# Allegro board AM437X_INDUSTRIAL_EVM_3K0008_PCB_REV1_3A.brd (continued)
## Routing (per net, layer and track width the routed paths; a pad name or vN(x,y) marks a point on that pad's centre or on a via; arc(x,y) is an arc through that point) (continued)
JTAG_TMS: length 66.6
  TOP w0.13: J7.1 v1(133.6,74.42) ; U11.Y24 84.72,74.62 84.72,78.06 85.2,78.55 v1(85.2,80.02)
  L3_SIG1 w0.13: v1(126.54,73.69) 125.78,72.92 121.94,72.92 120.24,74.61 110.81,74.61 v1(107.95,77.47)
  L4_SIG2 w0.13: v1(126.54,73.69) 129.31,70.92 130.1,70.92 v1(133.6,74.42)
  BOTTOM w0.13: v1(107.95,77.47) 105.23,77.47 103.94,78.76 103.94,79.86 102.19,81.61 98.43,81.61 96.69,79.86 94.02,79.86 93.47,80.41 86.11,80.41 85.71,80.01 85.21,80.01 v1(85.2,80.02) ; v1(126.54,73.69) 126.26,73.69 125.77,73.19 U45.11
JTAG_TRSTN: length 66.7
  TOP w0.13: U11.Y25 85.03,78.01 85.75,78.73 v1(85.75,80.8) ; J7.2 v1(128.4,74.42)
  L3_SIG1 w0.13: v1(106.3,77.98) 107.31,76.96 107.95,76.96 110.63,74.28 110.63,73.78 110.94,73.47 114.34,73.47 114.44,73.57 119.13,73.57 120.14,72.56 120.78,72.56 121.42,71.92 124.75,71.92 v1(125.73,70.94)
  L4_SIG2 w0.13: v1(128.4,74.42) 127.75,75.07 125.15,75.07 124.7,74.62 124.7,73.78 125.09,73.38 125.09,71.58 v1(125.73,70.94)
  BOTTOM w0.13: R433.2 v1(128.4,74.42) ; v1(125.73,70.94) 125.73,70.94 125.12,71.55 U45.10 ; v1(85.75,80.8) 85.76,80.79 93.7,80.79 94.33,80.17 96.5,80.17 98.24,81.91 103.07,81.91 104.49,80.49 104.49,79.15 105.66,77.98 v1(106.3,77.98)
JTAGPOD_DET: length 9.7
  TOP w0.13: v1(121.01,82.22) 120.52,82.7 120.52,84.15 120.2,84.47 U8.4
  BOTTOM w0.13: R421.1 124.87,78.36 v1(121.01,82.22)
MMC_CD: length 110.3
  TOP w0.13: v1(83.69,84.96) 83.82,84.84 R84.1
  L4_SIG2 w0.13: v1(46.99,40) 48.42,41.44 48.42,50.27 48.26,50.43 48.26,54.29 48.88,54.9 48.88,55.74 49.19,56.05 49.19,56.88 49.53,57.23 49.95,57.23 53.35,60.63 55.38,60.63 55.69,60.93 59.3,60.93 60.11,61.74 60.11,63.71 64.57,68.17 64.57,71.94 66.56,73.93 67.44,73.93 67.65,74.14 72.28,74.14 72.52,74.39 72.52,74.63 74.6,76.7 74.6,80.57 73.76,81.4 73.76,85.93 75.19,87.36 77.33,87.36 78.58,86.11 81.25,86.11 81.88,85.47 83.19,85.47 v1(83.69,84.96)
  BOTTOM w0.13: 52.88,19.17 53.21,19.5 53.21,21.21 52.61,21.81 52.61,23.48 54.36,25.22 54.36,34.29 51.24,37.41 50.27,37.41 49.71,37.97 48.39,37.97 46.99,39.37 v1(46.99,40) ; 52.88,19.17 53.48,18.57 54.31,18.57 54.49,18.39 54.49,17.15 54.23,16.89 R548.1 53.59,16.39 54.49,15.49 J19.10 ; 52.88,19.17 U59.3
MMC_CLK: length 67.8
  TOP w0.13: U27.1 v1(46.06,5.58) 45.72,5.92 45.72,6.73 46.1,7.11 51.78,7.11 54.48,9.82 54.48,15.11 54.71,15.34 54.71,17.81 55.65,18.75 55.65,20.22 56.74,21.3 56.74,24.14 55.89,24.98 55.89,30.09 56.24,30.43 56.24,30.94 56.39,31.09 57.15,31.09 57.3,31.25 57.3,31.46 57.15,31.61 56.39,31.61 56.24,31.77 56.24,31.98 56.39,32.14 57.15,32.14 57.3,32.29 57.3,32.5 57.15,32.66 56.39,32.66 56.24,32.81 56.24,33.03 56.39,33.18 57.15,33.18 57.3,33.33 57.3,33.55 57.15,33.7 56.39,33.7 56.24,33.85 56.24,41.41 59.49,44.65 59.49,48.13 60.25,48.89 R179.1
  BOTTOM w0.13: v1(46.06,5.58) 46.06,5.01 43.72,2.66 J19.5
MMC_CMD: length 66.7
  TOP w0.13: v1(52.83,9.02) 54.05,10.23 54.05,15.39 54.25,15.6 54.25,17.98 55.19,18.92 55.19,20.4 56.26,21.46 56.26,23.95 55.46,24.75 55.46,30.27 55.81,30.61 55.81,42.09 58.72,45.01 58.72,45.29 58.57,45.44 58.24,45.44 58.09,45.59 58.09,45.81 58.24,45.96 58.57,45.96 58.72,46.11 58.72,46.33 58.57,46.48 58.24,46.48 58.09,46.64 58.09,46.85 58.24,47 58.57,47 58.72,47.16 58.72,47.37 58.57,47.53 58.24,47.53 58.09,47.68 58.09,47.89 58.24,48.05 58.57,48.05 58.72,48.2 58.72,48.41 58.57,48.57 58.24,48.57 58.09,48.72 58.09,48.94 58.24,49.09 58.57,49.09 58.72,49.24 58.72,49.63 59.13,50.04 R177.1 ; v1(50.42,4.58) U27.7 ; R244.1 v1(51.05,9.02)
  L3_SIG1 w0.13: v1(52.83,9.02) v1(51.05,9.02) 50.42,8.38 v1(50.42,4.58)
  BOTTOM w0.13: J19.3 53.79,3.36 52.55,4.6 50.44,4.6 v1(50.42,4.58)
MMC_D0: length 68.6
  TOP w0.13: U27.2 45.46,5.08 v1(45.21,4.83) ; v1(45.21,4.83) R267.1 ; v1(45.21,4.83) 45.21,5.52 45.21,5.53 45.21,6.84 45.92,7.55 51.6,7.55 52.32,8.27 52.32,9.53 53.47,10.67 53.47,15.49 53.8,15.82 53.8,19.69 55.82,21.71 55.82,23.75 55.02,24.55 55.02,30.45 55.37,30.79 55.37,42.64 57.61,44.87 57.61,47.02 57.45,47.18 57.2,47.18 57.05,47.33 57.05,47.54 57.2,47.7 57.45,47.7 57.61,47.85 57.61,48.07 57.45,48.22 57.2,48.22 57.05,48.37 57.05,48.59 57.2,48.74 57.45,48.74 57.61,48.89 57.61,49.11 57.45,49.26 57.2,49.26 57.05,49.41 57.05,49.63 57.2,49.78 57.45,49.78 57.61,49.93 57.61,50.37 58.42,51.18 R174.1
  BOTTOM w0.13: v1(45.21,4.83) 44.45,4.06 J19.7
MMC_D1: length 72.6
  TOP w0.13: R167.1 57.35,52.32 56.59,51.56 56.59,51.14 56.44,50.99 55.8,50.99 55.65,50.83 55.65,50.62 55.8,50.47 56.44,50.47 56.59,50.31 56.59,50.1 56.44,49.94 55.8,49.94 55.65,49.79 55.65,49.58 55.8,49.42 56.44,49.42 56.59,49.27 56.59,44.47 54.94,42.82 54.94,30.97 54.59,30.63 54.59,24.3 55.39,23.5 55.39,21.91 53.34,19.86 53.34,16.05 53.01,15.73 53.01,10.98 51.82,9.78 51.82,8.51 51.31,8 43.69,8 42.54,6.86 42.54,5.53 42.55,5.52 v1(42.55,4.83) R266.1 43.94,4.19 45.34,4.19 45.72,4.58 U27.3
  BOTTOM w0.13: v1(42.55,4.83) 41.32,4.83 J19.8
MMC_D2: length 76.9
  TOP w0.13: U27.6 v1(49.02,4.08) ; R161.1 57.25,53.47 54.99,51.21 54.99,49.35 55.8,48.55 55.8,48.07 55.64,47.91 55.04,47.91 54.89,47.76 54.89,47.55 55.04,47.39 55.64,47.39 55.8,47.24 55.8,47.02 55.64,46.87 55.04,46.87 54.89,46.72 54.89,46.5 55.04,46.35 55.64,46.35 55.8,46.2 55.8,45.98 55.64,45.83 55.04,45.83 54.89,45.68 54.89,45.46 55.04,45.31 55.64,45.31 55.8,45.16 55.8,44.29 54.5,43 54.5,37.67 53.78,36.95 53.78,34.68 54.5,33.96 54.5,31.16 54.15,30.81 54.15,24.05 54.95,23.25 54.95,22.11 52.88,20.04 52.88,16.26 52.58,15.95 52.58,11.68 v1(51.05,10.16) R236.1
  L3_SIG1 w0.13: v1(51.05,10.16) 50.43,10.78 48.07,10.78 47.5,10.21 47.5,7.37 49.02,5.84 v1(49.02,4.08) 50.62,4.08 51.31,4.76 v1(54.74,4.76)
  BOTTOM w0.13: J19.1 v1(54.74,4.76)
MMC_D3: length 72.6
  TOP w0.13: U27.8 v1(49.66,5.08) ; R231.1 v1(51.05,11.43) 52.07,12.45 52.07,16.15 52.43,16.51 52.43,21.31 53.72,22.6 53.72,30.99 54.07,31.34 54.07,33.78 53.21,34.63 53.21,36.99 54.07,37.85 54.07,43.18 54.43,43.55 54.43,49.22 54.28,49.37 53.52,49.37 53.37,49.53 53.37,49.74 53.52,49.89 54.28,49.89 54.43,50.05 54.43,50.26 54.28,50.41 53.52,50.41 53.37,50.57 53.37,50.78 53.52,50.94 54.28,50.94 54.43,51.09 54.43,51.51 56.9,53.98 61.6,53.98 R158.1
  L3_SIG1 w0.13: v1(51.05,11.43) 52.07,10.41 52.07,9.91 51.72,9.55 50.07,9.55 49.66,9.14 v1(49.66,5.08)
  BOTTOM w0.13: J19.2 55.77,4.06 53.85,4.06 52.84,5.08 v1(49.66,5.08)
MOT1_ADC: length 201
  TOP w0.13: v2(108.84,73.91) 107.15,72.23 107.15,70.73 106.8,70.38 106.8,69.33 105.5,68.04 103.54,68.04 v2(103.25,68.33)
  TOP w0.203: U11.Y13 84.7,67.48 v1(84.7,67.5)
  L3_SIG1 w0.13: v1(26.39,9.24) 27.83,7.8 41.99,7.8 46.5,12.31 50.93,12.31 52.7,10.54 52.7,9.9 56.38,6.23 66.05,6.23 67.58,7.77 69.47,7.77 70.9,9.19 75.51,9.19 77.84,6.87 88.67,6.87 88.85,7.05 103.75,7.05 105.95,9.26 105.95,11.43 109.66,15.13 109.66,20.28 111.87,22.49 111.87,24.38 115.37,27.89 120.9,27.89 122.17,29.16 v1(122.17,31.06) ; v1(84.7,67.5) 85.35,66.85 97.71,66.85 98.55,67.69 102.62,67.69 v2(103.25,68.33)
  L4_SIG2 w0.13: v2(103.25,68.33) 104.01,68.33 104.96,67.38 105.35,67.38 106.56,66.17 107.92,66.17 108.67,65.42 110.51,65.42 111.83,64.09 111.83,63.39 115.4,59.82 115.4,55.72 117.04,54.09 117.04,48.43 115.88,47.28 115.88,39.83 117.18,38.53 117.18,35.28 118.02,34.44 120.39,34.44 122.17,32.66 v1(122.17,31.06)
  BOTTOM w0.13: R561.2 v1(26.39,9.24)
  BOTTOM w0.254: R435.2 v2(108.84,73.91)
MOT1_LEVEL: length 3.4
  BOTTOM w0.13: R561.1 R562.1 C349.1 R554.2
MOT2_ADC: length 177.9
  TOP w0.13: U11.AD13 87.94,66.84 89.5,66.84 90.04,66.29 94.64,66.29 95.47,67.12 100.24,67.12 100.76,66.6 v1(104.27,66.6) R129.2
  L3_SIG1 w0.13: v1(31.74,9.15) 39.81,9.15 43.59,12.93 51.19,12.93 53.32,10.79 53.32,10.16 56.63,6.85 65.79,6.85 67.33,8.38 69.22,8.38 70.64,9.81 75.77,9.81 76.7,8.88 76.91,8.67 77.25,8.32 90.47,8.32 91.12,7.67 103.49,7.67 105.34,9.51 105.34,11.68 109.05,15.39 109.05,20.54 111.25,22.74 111.25,24.64 115.12,28.51 119.62,28.51 v1(120.5,29.39)
  L4_SIG2 w0.13: v1(104.27,66.6) 104.76,66.11 105.27,66.11 105.6,65.77 105.6,65.4 106.29,64.7 106.81,64.7 106.9,64.8 110.25,64.8 111.22,63.84 111.22,63.13 114.79,59.56 114.79,54.22 115.08,53.93 115.08,50.54 115.79,49.84 115.79,48.06 114.91,47.18 114.91,44.8 115.27,44.44 115.27,39.57 116.54,38.3 116.54,34.99 117.15,34.39 117.9,33.63 120.32,33.63 120.83,33.12 120.83,29.72 v1(120.5,29.39)
  BOTTOM w0.13: R563.2 v1(31.74,9.15)
MOT2_LEVEL: length 3.4
  BOTTOM w0.13: R563.1 R564.1 R555.2 C350.1
MOT3_ADC: length 175.7
  TOP w0.13: U11.AE13 89.82,67.15 90.42,66.55 94.46,66.55 95.34,67.43 100.5,67.43 v1(101.27,68.2) 101.32,68.2 102.21,69.09 103.76,69.09 R124.2
  L3_SIG1 w0.13: v1(121.51,29.77) 121.51,29.39 120.32,28.2 115.25,28.2 111.56,24.51 111.56,22.62 109.35,20.41 109.35,15.26 105.65,11.55 105.65,9.38 103.62,7.36 91,7.36 90.34,8.02 77.13,8.02 75.64,9.5 70.77,9.5 69.34,8.07 67.46,8.07 65.92,6.54 56.5,6.54 53.01,10.03 53.01,10.67 51.06,12.62 45.83,12.62 41.72,8.51 v1(38.73,8.51)
  L4_SIG2 w0.13: v1(121.51,29.77) 121.51,32.88 120.46,33.94 118.03,33.94 117.96,34 116.85,35.12 116.85,38.43 115.58,39.7 115.58,47.41 116.66,48.49 116.66,52.79 115.09,54.35 115.09,59.69 111.52,63.26 111.52,63.97 110.38,65.11 108.4,65.11 107.66,65.85 105.96,65.85 104.74,67.07 104.07,67.07 103.78,66.78 102.72,66.78 101.3,68.2 v1(101.27,68.2)
  BOTTOM w0.13: R558.2 v1(38.73,8.51)
MOT3_LEVEL: length 3.4
  BOTTOM w0.13: C348.1 R553.2 R559.1 R558.1
MOT_OUT1: length 2.3
  TOP w0.254: U23.5 40.79,26.67
MOT_OUT2: length 2.3
  TOP w0.305: U23.8 42.74,27.12 42.42,26.8
MOT_OUT3: length 2.9
  TOP w0.305: U23.9 43.39,27.35 44.32,26.42
MOT_PGND1: length 36.3
  TOP w0.305: v1(41.61,26.92) 41.61,27.3 41.44,27.47 U23.6
  TOP w0.508: R195.2 v1(57.78,34.54)
  L4_SIG2 w0.508: v1(41.61,26.92) 41.61,25.2 45.8,21.01 52.88,21.01 v3(54.36,22.48)
  BOTTOM w0.508: v3(54.36,22.48) 55.69,23.81 55.69,33.33 56.9,34.54 v1(57.78,34.54) C308.1 ; R538.1 40.41,25.93 41.4,26.92 v1(41.61,26.92)
MOT_PGND2: length 25.8
  TOP w0.305: v1(42.09,27.79) U23.7
  TOP w0.508: R193.2 v1(25.27,34.42)
  L3_SIG1 w0.508: v1(42.09,27.79) 42.06,27.79 41.33,28.52 38.76,28.52 37.08,30.2 37.08,31.8 34.47,34.42 v1(25.27,34.42)
  BOTTOM w0.508: R193.2 v1(25.27,34.42) ; v1(42.09,27.79) 42.55,27.34 42.55,26.57 R537.1
MOT_PGND3: length 21
  TOP w0.305: v1(44.3,27.58) 44.04,27.84 U23.10
  TOP w0.508: R211.2 v1(57.25,25.5)
  L4_SIG2 w0.508: v1(44.3,27.58) 44.3,27.46 45.09,26.67 48.13,26.67 51.05,23.75 52.45,23.75 52.53,23.83 52.53,23.83 53.22,24.51 56.26,24.51 v1(57.25,25.5)
  BOTTOM w0.381: v1(44.3,27.58) 44.3,27.3 45.66,25.93 R536.1
  BOTTOM w0.508: R211.2 v1(57.25,25.5)
MOT_PGNDTOTAL: length 32.1
  TOP w0.508: R200.2 v3(26.16,31.5) ; R215.1 v3(47.62,22.61) ; 52.45,28.83 v3(52.45,28.05) ; R203.2 v3(58.93,31.12) ; R222.2 v3(58.93,21.84)
  L3_SIG1 w0.508: v3(24.38,36.32) 24.38,33.27 v3(26.16,31.5) 29.08,28.58 34.29,28.58 v3(40.64,22.23)
  BOTTOM w0.508: 52.45,28.83 v3(52.45,28.05) ; C332.2 57.44,27.05 v3(57.06,27.43) ; v3(58.93,32.89) 58.67,32.64 C308.2 ; C300.2 v3(24.38,36.32)
MOTOR_OUT1: length 7.2
  TOP w0.508: J17.1 25.78,5.34 ; J17.1 25.78,3.05 ; J17.1 23.49,3.05 ; J17.1 23.49,5.34
  BOTTOM w0.508: R562.2 v3(23.71,9.24)
MOTOR_OUT2: length 5.7
  TOP w0.508: 28.86,5.05 J17.2 ; J17.2 30.58,5.05 ; J17.2 30.58,3.33 ; J17.2 28.86,3.33
  BOTTOM w0.508: R564.2 v3(28.96,9.15)
MOTOR_OUT3: length 5.8
  TOP w0.508: 33.94,5.05 J17.3 ; J17.3 33.94,3.33 ; J17.3 35.66,5.05 ; J17.3 35.66,3.33
  BOTTOM w0.508: R559.2 v3(37.59,8.51)
MOTVM_ADC: length 11.8
  TOP w0.13: v1(103.76,58.17) C68.1 R154.1
  BOTTOM w0.13: R476.2 103.63,58.04 v1(103.76,58.17) 104.52,58.93 104.52,62.86 R454.1
MTR_FAULT: length 386.4
  TOP w0.13: R245.2 v1(83.95,10.54) ; v1(44.69,35.81) U23.18 ; v1(75.94,66.32) U11.F11 ; R62.2 R61.2 R60.2 82.68,92.58 83.44,93.34 v1(83.44,96.14) ; v1(40.77,40.64) 41.78,39.62 R186.1
  L3_SIG1 w0.13: v1(31.88,44.7) 28.03,48.55 28.03,53.05 26.08,54.99 23.75,54.99 20.1,58.64 20.1,61.98 17.25,64.83 17.25,65.56 16.23,66.58 14.83,66.58 13.56,67.85 12.76,67.85 11.75,68.86 11.75,77.54 10.92,78.36 10.92,81.85 11.75,82.68 11.75,84.39 10.03,86.11 10.03,96.77 11.57,98.31 11.57,99.81 10.66,100.72 3.92,100.72 2.29,102.36 2.29,109.09 3.76,110.56 9.61,110.56 13.08,114.04 19.37,114.04 21.87,111.54 21.87,107.47 24.4,104.94 25.73,104.94 28.75,107.95 42.19,107.95 45.37,104.77 56.25,104.77 59.56,108.08 63.32,108.08 64.91,109.67 79.87,109.67 81.91,107.62 v1(81.91,106.68)
  L4_SIG2 w0.13: v1(81.91,106.68) 82.05,106.54 82.05,102.23 82.19,102.09 82.19,97.38 v1(83.44,96.14) ; v1(83.95,10.54) 87.12,13.72 90.3,13.72 93.73,17.14 93.73,21.59 97.65,25.52 97.65,32.33 97.13,32.86 97.13,34.82 96.57,35.38 95.8,35.38 93.99,37.18 93.99,37.19 93.64,37.54 93.64,37.95 91.55,40.04 91.55,40.48 90.82,41.22 90.82,47.28 89.9,48.2 88.6,48.2 87.74,49.05 87.74,53.34 86.7,54.38 86.7,58.05 86.18,58.57 86.18,60.8 86.18,60.8 86.18,61.13 87.02,61.97 87.02,63.43 85.53,64.92 82.61,64.92 82.29,64.59 77.87,64.59 76.67,65.79 76.46,65.79 v1(75.94,66.32) ; v1(44.69,35.81) 44.69,34.79 44.14,34.24 37.09,34.24 31.88,39.45 v1(31.88,44.7)
  BOTTOM w0.13: Q10.G 38.61,41.34 38.61,40 40.13,40 v1(40.77,40.64) 41.91,40.64 44.69,37.86 v1(44.69,35.81) 44.73,35.85 46.52,35.85 48.25,37.58 49.66,37.58 50.14,37.1 51.04,37.1 53.96,34.17 53.96,25.27 49.4,20.7 49.4,15.21 56.87,7.75 62.57,7.75 63.78,8.96 70.43,8.96 71.27,9.8 82.31,9.8 83.06,10.54 v1(83.95,10.54)
MTRA_GND: length 8.7
  L3_SIG1 w0.508: 13.49,37.44 J10.1 ; J10.1 15.13,39.09 ; J10.1 15.13,37.44 ; 10.5,39.96 J10.5 8.85,41.61
  BOTTOM w0.508: C270.2 v3(7.37,48.64) ; v3(19.04,29.08) R513.1 v3(18.03,30.1)
OSC0_IN: length 6.4
  TOP w0.13: R92.2 R82.2 C36.1 72.99,86.83 72.99,88.61 74.05,89.67 Y1.3
OSC0_OUT: length 4.4
  TOP w0.13: Y1.1 71.95,88.07 72.36,87.66 C35.1 72.48,86.2 R82.1 R91.2
PHY1_LED_ACTN: length 39.9
  TOP w0.13: v1(48.47,93.13) 48.48,93.12 49,93.12 R53.2
  L3_SIG1 w0.13: v1(35.69,115.7) 35.69,114.07 39.9,109.86 41.22,109.86 43.63,107.44 v1(46.2,107.44)
  BOTTOM w0.13: U37.17 48.09,93.46 48.43,93.13 v1(48.47,93.13) 48.62,92.98 49.13,92.98 R53.2 49.53,93.09 49.53,93.15 49.98,93.6 50.04,93.6 50.06,93.62 52.48,93.62 53.04,94.19 53.04,99.93 46.2,106.77 v1(46.2,107.44) ; R270.1 v1(35.69,115.7)
PHY1_LED_LINKN: length 33.7
  TOP w0.13: v1(48.64,96.27) R45.2
  L3_SIG1 w0.13: v1(36.83,115.7) 36.83,113.59 40.19,110.24 41.27,110.24 43.31,108.2 v1(46.18,108.2)
  BOTTOM w0.13: v1(48.64,96.27) 49.45,97.07 49.45,103 45.71,106.74 45.71,107.73 v1(46.18,108.2) ; v1(48.64,96.27) R45.2 ; v1(48.64,96.27) 48.64,95.12 47.98,94.46 U37.15 ; R269.1 v1(36.83,115.7)
PORZ_RELEASE: length 101.7
  TOP w0.13: v1(66.88,10.46) 65.9,11.45 U26.16
  L3_SIG1 w0.13: v1(137.16,39.12) 130.18,32.13 122.24,32.13 118.92,28.81 114.99,28.81 110.94,24.77 110.94,22.87 108.74,20.67 108.74,17.71 105.03,14 105.03,10.87 103.11,8.96 100.63,8.96 99.65,7.97 91.25,7.97 90.6,8.63 77.38,8.63 75.56,10.45 66.89,10.45 v1(66.88,10.46)
  BOTTOM w0.13: v1(137.16,39.12) 136.78,39.5 136.78,46.48 135.89,47.37 R487.1
PORZN: length 158.8
  TOP w0.13: R90.2 v1(85.6,85.09) 85.72,85.22 R75.1
  L3_SIG1 w0.13: v1(65.32,79.17) 65.43,79.06 66.07,79.06 66.53,79.52 66.53,80.49 65.62,81.39 65.62,85.61 65.14,86.09 65.14,87.67 65.84,88.37 68.4,88.37 70.15,90.12 v1(76.45,90.12) ; v1(120.78,34.85) 122.73,32.89 129.92,32.89 v1(136.02,38.99)
  L4_SIG2 w0.13: v1(85.6,85.09) 86.61,85.09 86.87,84.84 91.19,84.84 95.91,80.11 96.56,80.11 98.38,78.29 99.42,78.29 99.89,77.82 99.89,75.02 100.44,74.47 100.44,71.39 101.12,70.71 102.75,70.71 103.53,69.93 103.53,69.46 105.13,67.87 106.65,67.87 108.44,66.08 v2(109.69,66.08) 110.29,66.08 112.14,64.22 112.14,63.88 115.71,60.31 115.71,55.85 117.34,54.22 117.34,48.31 116.19,47.15 116.19,39.95 117.49,38.66 117.49,35.41 118.05,34.85 v1(120.78,34.85)
  BOTTOM w0.13: U54.2 134.49,45.72 R487.2 134.11,46.61 136.02,46.61 136.4,46.23 136.4,39.37 v1(136.02,38.99) ; v1(76.45,90.12) 78.87,87.7 81.73,87.7 82.07,88.04 84.3,88.04 85.6,86.74 v1(85.6,85.09) ; v1(65.32,79.17) 65.29,79.2 65.07,79.2 64.26,80.01 63.03,80.01 61.86,78.84 60.48,78.84 R416.2 ; v2(109.69,66.08) 109.69,65.68 109.22,65.21 109.22,63.5 108.46,62.74 108.46,61.85 107.7,61.09 107.7,59.31 107.44,59.05 U48.2
PR1_EDC_SYNC0_OUT: length 227.6
  TOP w0.13: v1(47.62,47.88) 47.62,46.18 44.18,42.73 39.35,42.73 38.48,41.86 32.18,41.86 31.12,42.93 27.81,42.93 26.67,41.78 24.64,41.78 22.48,39.62 22.48,35.36 v1(20.83,33.71) ; v1(81.15,88.27) R72.2
  L3_SIG1 w0.13: v1(20.83,33.71) 20.5,33.38 20.5,32.46 22.48,30.48 22.48,29.32 20,26.84 20,24.7 21.41,23.3 21.41,2.54 22.6,1.35 36.2,1.35 37.07,2.22 40.37,2.22 40.66,1.94 53.75,1.94 54.17,2.35 55.84,2.35 56.85,1.34 108.84,1.34 J16.18
  L4_SIG2 w0.13: v1(81.15,88.27) 79.26,90.15 77.6,90.15 76.78,89.34 74.83,89.34 72.22,86.73 72.22,82.27 67.86,77.91 67.86,75.66 67.06,74.85 66.18,74.85 63.64,72.32 63.64,70.68 61.34,68.37 61.34,67.49 57.52,63.68 57.13,63.68 55,61.55 51.92,61.55 47.96,57.59 47.95,57.19 47.95,55.29 47.34,54.67 47.34,50.05 47.36,50.02 47.36,49.27 46.99,48.89 46.99,48.51 v1(47.62,47.88)
PR1_EDC_SYNC1_OUT: length 197.1
  TOP w0.13: v1(39.37,43.31) 39.37,44.45 41.91,46.99 45.97,46.99 v1(47.62,48.64) ; v1(79.12,88.27) 79.5,87.88 R71.2 ; R256.1 v1(110.24,10.16)
  L3_SIG1 w0.13: v1(39.37,43.31) 38.48,42.42 37.34,42.42 35.92,41 35.92,35.98 37.84,34.05 39.75,34.05 40.45,33.36 40.45,30.12 41.23,29.34 41.78,29.34 42.81,28.31 42.81,22.09 47.37,17.53 51.99,17.53 52.4,17.12 52.4,15.6 56.94,11.06 60.74,11.06 v1(61.16,10.64)
  L4_SIG2 w0.13: v1(61.16,10.64) 60.45,9.93 60.45,9.02 63.23,6.24 65.42,6.24 65.86,5.79 65.86,2.59 66.42,2.03 115.27,2.03 116.33,3.1 116.33,4.32 115.79,4.86 114.94,4.86 114.33,5.48 114.33,6.25 113.75,6.82 113.57,6.82 v1(110.24,10.16) ; v1(47.62,48.64) 47.81,48.82 47.81,50.01 47.64,50.18 47.64,54.54 48.26,55.16 48.26,56.43 48.26,56.83 49.53,58.1 49.95,58.1 53.09,61.24 55.13,61.24 55.44,61.55 56.18,61.55 59.69,65.06 60.52,65.06 63.95,68.49 63.95,72.19 66.31,74.55 67.18,74.55 68.17,75.53 68.17,77.78 72.56,82.17 72.56,86.63 74.96,89.03 78.18,89.03 78.38,88.83 78.55,88.83 v1(79.12,88.27)
PR1_EDIO_DATA6: length 160.2
  TOP w0.13: U11.B9 73.03,64.24 70.19,64.24 69.05,63.1 65.03,63.1 64.86,63.27 62.46,63.27 v1(61.85,63.88)
  L3_SIG1 w0.13: v1(61.85,63.88) 63.88,63.88 64.37,63.39 64.37,58.08 61.22,54.93 57.49,54.93 57.18,55.24 52.32,55.24 51.88,54.8 40.73,54.8 37.82,51.89 37.82,47.02 34.04,43.24 29.46,43.24 26.98,45.72 26.98,48.9 22.35,53.52 14.35,53.52 11.38,50.55 v1(9.27,50.55)
  BOTTOM w0.13: J3.6 8.38,106.43 8.38,102.89 11.68,99.59 11.68,97.28 9.93,95.53 9.93,86.01 11.54,84.4 11.54,80.92 13.23,79.23 13.23,75.71 10.44,72.92 10.44,62.84 12.52,60.76 12.52,57.58 11.58,56.64 8.38,56.64 7.24,55.5 7.24,52.58 v1(9.27,50.55)
PR1_EDIO_DATA7: length 159.3
  TOP w0.13: U11.F10 75.94,65.17 v1(76.33,64.77)
  L3_SIG1 w0.13: v1(10.92,49.66) 14.48,53.21 22.23,53.21 26.67,48.77 26.67,45.59 29.33,42.93 34.17,42.93 38.13,46.89 38.13,51.76 40.85,54.48 47.65,54.48 48.8,53.33 51.3,53.33 52.9,54.93 56.04,54.93 56.69,54.28 61.01,54.28 64.68,57.95 64.68,62.43 65.89,63.64 69.23,63.64 70.92,65.34 75.77,65.34 v1(76.33,64.77)
  BOTTOM w0.13: J3.8 13.39,106.5 13.39,99.24 12.95,98.81 12.95,98.04 10.29,95.38 10.29,86.13 12.52,83.9 12.52,82.28 11.85,81.6 11.85,81.12 13.59,79.38 13.59,75.56 10.79,72.77 10.79,62.99 12.85,60.93 12.85,57.35 11.79,56.29 8.53,56.29 7.6,55.35 7.6,52.98 v1(10.92,49.66)
PRU0_ENDAT0_CLK: length 220.8
  L3_SIG1 w0.13: J16.31 98.33,4.86 98.33,3.44 96.84,1.95 68.65,1.95 66.19,4.41 62.81,4.41 60.32,1.91 56.71,1.91 55.96,2.66 54.04,2.66 53.62,2.24 40.79,2.24 40.4,2.62 37.03,2.62 36.07,1.66 30.09,1.66 22.92,8.83 22.92,31.34 21.74,32.52 21.74,38.96 20.95,39.75 20.95,44.07 v1(21.46,44.58)
  L4_SIG2 w0.13: J16.31 98.73,7.22 101.83,7.22 105.28,10.67 105.28,13.32 104.69,13.92 104.69,19.12 105.5,19.94 105.5,21.79 106.55,22.83 106.55,23.57 106.55,25.82 107.66,26.93 107.66,28.88 105.67,30.86 105.67,35.05 105.37,35.36 105.37,37.23 105.37,43.26 103.31,45.31 103.31,49.87 101.61,51.58 101.61,52.96 100.45,54.12 100.45,56.29 99.51,57.22 99.51,58.75 99.2,59.07 95.09,63.17 95.09,64.01 92.89,66.21 92.89,70.53 89.5,73.91 89.5,75.11 88.41,76.2 v2(86.87,76.2)
  BOTTOM w0.13: R428.1 93.08,74.02 88.66,74.02 87.82,74.85 87.82,75.25 v2(86.87,76.2) 86.87,76.52 86.56,76.82 R422.1 ; v1(21.46,44.58) 20.95,44.07 R493.2
PRU0_ENDAT0_OUT: length 220.8
  L3_SIG1 w0.13: v1(31.12,24.77) 31.12,19.66 24.99,13.54 24.99,8.68 27.88,5.79 39.75,5.79 42.99,2.55 53.5,2.55 54.18,3.24 57.01,3.24 58.02,2.22 60.19,2.22 62.68,4.72 66.32,4.72 68.78,2.26 95.15,2.26 96.33,3.44 96.33,4.86 J16.33
  L4_SIG2 w0.13: J16.33 96.33,4.86 100.04,4.86 100.37,5.19 100.37,6.25 101.04,6.91 101.96,6.91 105.71,10.67 105.71,13.32 104.99,14.04 104.99,18.99 105.81,19.81 105.81,21.66 106.85,22.7 106.85,23.7 106.85,23.7 106.85,25.7 107.96,26.81 107.96,29.05 105.98,31.03 105.98,35.18 105.67,35.49 105.67,37.1 105.67,40.35 106.02,40.7 106.02,43.04 103.62,45.44 103.62,50 101.92,51.71 101.92,53.08 100.76,54.24 100.76,56.42 99.82,57.35 99.82,58.88 99.5,59.19 95.4,63.3 95.4,64.14 93.2,66.34 93.2,70.65 89.73,74.12 89.73,75.2 88.29,76.65 86.68,76.65 86.42,76.38 86.42,75.88 v2(86.74,75.56)
  BOTTOM w0.13: R427.1 94.63,73.79 88.52,73.79 v2(86.74,75.56) 85.46,75.56 R423.1 ; v1(31.12,24.77) 28.7,24.77 27.56,23.62 16.9,23.62 R540.2
PRU0_ENDAT1_CLK: length 5.4
  TOP w0.13: R252.2 98.33,7.4 98.33,4.82 J16.32
PRU0_ENDAT1_IN: length 4.9
  TOP w0.13: R249.2 92.33,8.38 92.33,4.82 J16.38
PRU0_ENDAT1_OUT: length 5.3
  TOP w0.13: J16.34 96.37,4.86 96.37,7.64 R251.2
PRU0_ENDAT1_OUTEN: length 5
  TOP w0.13: R250.2 94.33,8.35 94.33,4.82 J16.36
PRU0_ENDAT2_CLK: length 5.9
  TOP w0.13: J16.52 77.98,4.47 77.98,4.91 78.37,5.3 78.37,9.26 R242.2
PRU0_ENDAT2_IN: length 5.9
  TOP w0.13: J16.58 72.37,4.86 72.37,9.25 R238.2
PRU0_ENDAT2_OUT: length 5.8
  TOP w0.13: R240.2 76.33,9.27 76.33,4.82 J16.54
PRU0_ENDAT2_OUTEN: length 6.2
  TOP w0.13: R239.2 75.31,7.84 74.33,6.86 74.33,4.82 J16.56
PRUETH0_25MHZCLK: length 31.1
  TOP w0.13: v1(29.46,86.36) 29.46,87.25 28.81,87.9 U7.23
  L3_SIG1 w0.13: v1(18.03,101.85) 18.54,101.35 18.54,87.5 20.12,85.93 25.7,85.93 26.8,84.84 28.56,84.84 29.46,85.74 v1(29.46,86.36)
  BOTTOM w0.13: R311.2 v1(18.03,101.85)
PRUETH0_COL: length 85.1
  TOP w0.13: 32.89,91.19 32.26,90.55 ; 32.26,90.55 31.28,91.53 U7.29 ; 32.26,90.55 v1(32.28,90.53) ; v1(13.42,98.62) 8.43,93.62 6.38,93.62 v1(3.56,90.8)
  L3_SIG1 w0.13: v1(32.28,90.53) 32.64,90.17 32.64,87.17 31.27,85.8 31.27,84 34.42,80.85 34.42,78.49 35.5,77.41 45.91,77.41 48.92,74.39 50.62,74.39 51.73,73.28 55.96,73.28 56.41,73.74 57.71,73.74 v1(58.17,73.28)
  BOTTOM w0.13: R352.2 v1(3.56,90.8) ; v1(13.42,98.62) 15.32,96.72 19.82,96.72 20.13,97.03 23.14,97.03 24.03,96.14 29.26,96.14 29.69,95.71 29.69,93.75 30.16,93.28 30.74,93.28 31.31,92.72 31.31,91.5 v1(32.28,90.53) 32.69,90.93 32.89,90.93 ; v1(58.17,73.28) 58.48,73.28 58.95,73.75 59.53,73.75 R434.1
PRUETH0_CRS: length 3.7
  TOP w0.13: 32.89,88.61 30.98,90.53 U7.27
PRUETH0_INT: length 3
  TOP w0.13: TP3.1 25.5,96.36 25.81,96.05 U7.8
PRUETH0_LINKLED: length 29.8
  TOP w0.13: v1(7.87,89.28) 8.76,89.28 13.21,84.84 18.17,84.84 21.73,88.39 22.61,88.39 24.26,86.75 R77.1 24.71,87.19 24.71,88.21 25.31,88.81 U7.17
  BOTTOM w0.13: v1(7.87,89.28) 5.21,91.95 R348.2
PRUETH0_MDC: length 2.3
  TOP w0.13: U7.20 27.31,87.76 27.05,87.5 27.05,87.12 R79.1
PRUETH0_MDIO: length 2.5
  TOP w0.13: R78.1 26.81,87.9 U7.19
PRUETH0_RESETN: length 12.8
  TOP w0.13: U7.18 26.31,88.16 26.03,87.88 25.4,87.88 25.02,87.5 25.02,86.04 25.02,86.04 25.02,85.41 25.02,85.41 25.02,84.45 v1(24.38,83.82)
  BOTTOM w0.13: v1(24.38,83.82) 24,83.82 23.13,84.7 21.71,84.7 21.41,84.4 21.41,82.57 21.58,82.41 U43.4
PRUETH0_RXCLK: length 4.7
  TOP w0.13: 32.89,86.36 31.82,87.43 31.82,88.32 30.61,89.53 U7.25
PRUETH0_RXD0: length 3.7
  TOP w0.13: U7.30 32.03,92.03 v1(32.16,92.17) 32.86,92.17 32.89,92.2
  BOTTOM w0.13: v1(32.16,92.17) 32.86,92.17 32.89,92.2
PRUETH0_RXD1: length 4.1
  TOP w0.13: U7.31 31.25,92.53 v1(32.04,93.31) 32.86,93.31 32.89,93.34
  BOTTOM w0.13: v1(32.04,93.31) 32.86,93.31 32.89,93.34
PRUETH0_RXD2: length 4.4
  TOP w0.13: U7.32 30.55,93.03 v1(32,94.49) 32.89,94.49
  BOTTOM w0.13: 32.89,94.49 v1(32,94.49)
PRUETH0_RXD3: length 5.9
  TOP w0.13: U7.1 29.31,95.1 29.84,95.63 v1(32.13,95.63) 32.89,95.63
  BOTTOM w0.13: 32.89,95.63 v1(32.13,95.63)
PRUETH0_RXDV: length 4.1
  TOP w0.13: 32.89,87.5 32.26,88.14 32.26,88.52 30.75,90.03 U7.26
PRUETH0_RXERR: length 3.4
  TOP w0.13: U7.28 31.09,91.03 32.37,89.76 32.89,89.76
PRUETH0_TXCLK: length 69.5
  TOP w0.13: U7.2 v1(28.81,94.59)
  L3_SIG1 w0.13: v1(59.25,80.64) 59.23,80.63 59.23,78.82 58.8,78.38 58.16,78.38 57.82,78.05 57.82,77.51 57.39,77.07 56.97,77.07 56.81,77.23 56.81,78.77 56.66,78.92 56.45,78.92 56.29,78.77 56.29,77.23 56.14,77.07 54.1,77.07 53.94,77.23 53.94,78 53.79,78.16 53.58,78.16 53.42,78 53.42,77.23 53.27,77.07 52.87,77.07 50.33,79.61 49.3,79.61 49.15,79.46 49.15,78.84 49,78.69 48.78,78.69 48.63,78.84 48.63,79.46 48.47,79.61 48.26,79.61 48.11,79.46 48.11,78.84 47.95,78.69 47.74,78.69 47.58,78.84 47.58,79.46 47.43,79.61 47.22,79.61 47.06,79.46 47.06,78.84 46.91,78.69 46.69,78.69 46.54,78.84 46.54,79.46 46.39,79.61 46.17,79.61 46.02,79.46 46.02,78.84 45.87,78.69 45.65,78.69 45.5,78.84 45.5,79.46 45.35,79.61 45.13,79.61 44.98,79.46 44.98,78.84 44.83,78.69 44.61,78.69 44.46,78.84 44.46,79.46 44.3,79.61 44.09,79.61 43.94,79.46 43.94,78.84 43.78,78.69 43.57,78.69 43.41,78.84 43.41,79.46 43.26,79.61 42.43,79.61 42.05,79.99 42.05,80.21 43.21,81.37 43.21,81.58 43.06,81.74 42.84,81.74 41.68,80.57 41.46,80.57 40.46,81.57 40.46,81.79 41.37,82.7 41.37,82.91 41.22,83.06 41,83.06 40.09,82.16 39.88,82.16 39.73,82.31 39.73,82.53 40.63,83.43 40.63,83.65 40.48,83.8 40.26,83.8 39.36,82.89 39.14,82.89 39,83.04 39,84.56 38.76,84.8 34.71,84.8 33.07,86.43 33.07,90.4 32.48,91 30.8,91 28.81,92.98 v1(28.81,94.59)
  BOTTOM w0.13: R410.1 v1(59.25,80.64)
PRUETH0_TXD0: length 60.8
  TOP w0.13: U7.4 v1(27.81,94.59)
  L3_SIG1 w0.13: v1(27.81,94.59) 27.56,94.84 27.56,95.54 28.13,96.1 29.48,96.1 30.15,95.43 30.15,93.82 30.38,93.6 30.6,93.6 30.87,93.88 31.09,93.88 31.24,93.72 31.24,93.51 30.96,93.23 30.96,93.01 31.34,92.64 32.36,92.64 32.64,92.36 32.64,92.07 33.21,91.5 33.94,90.76 33.94,88.13 35.67,86.41 36.25,86.41 36.4,86.56 36.4,86.97 36.55,87.12 36.77,87.12 36.92,86.97 36.92,86.56 37.07,86.41 37.29,86.41 37.44,86.56 37.44,86.97 37.6,87.12 37.81,87.12 37.96,86.97 37.96,86.56 38.12,86.41 40.69,86.41 41.46,85.63 42.09,85.63 42.24,85.48 42.24,85.04 42.4,84.89 42.61,84.89 42.76,85.04 42.76,85.48 42.92,85.63 43.13,85.63 43.29,85.48 43.29,85.04 43.44,84.89 43.65,84.89 43.81,85.04 43.81,85.48 43.96,85.63 44.18,85.63 44.33,85.48 44.33,85.04 44.48,84.89 44.7,84.89 44.85,85.04 44.85,85.48 45,85.63 45.22,85.63 45.37,85.48 45.37,85.04 45.52,84.89 45.74,84.89 45.89,85.04 45.89,85.48 46.04,85.63 46.53,85.63 47.24,84.92 47.24,83.83 47.09,83.68 44.96,83.68 44.81,83.53 44.81,83.31 44.96,83.16 47.09,83.16 47.24,83.01 47.24,81.66 47.36,81.54 47.66,81.54 47.81,81.69 47.81,83.64 47.96,83.79 48.18,83.79 48.33,83.64 48.33,81.69 48.48,81.54 49.72,81.54 49.87,81.69 49.87,81.81 50.02,81.97 50.24,81.97 50.39,81.81 50.39,81.69 50.54,81.54 50.76,81.54 50.91,81.69 50.91,81.81 51.06,81.97 51.28,81.97 51.43,81.81 51.43,81.69 51.59,81.54 51.8,81.54 51.95,81.69 51.95,81.81 52.11,81.97 52.32,81.97 52.48,81.81 52.48,81.69 52.63,81.54 53.98,81.54 54.74,82.3 54.74,82.55 55.75,83.57 v1(55.75,83.69)
  BOTTOM w0.13: v1(55.75,83.69) 56.13,83.69 56.52,83.31
PRUETH0_TXD1: length 59.2
  TOP w0.13: v1(27.28,96.65) 27.31,96.62 U7.5
  L3_SIG1 w0.13: v1(55.6,84.84) 55.15,84.38 49.94,84.38 49.78,84.54 49.11,84.54 46.83,86.81 45.44,86.81 45.08,87.17 43.41,87.17 42.96,87.62 42.41,87.62 41.49,88.53 38.74,88.53 38.42,88.85 37.09,88.85 33.51,92.43 33.51,93.13 32.67,93.96 32.67,94.69 32.2,95.16 31.94,95.16 31.66,95.44 31.66,95.89 32.13,96.35 32.13,97.56 31.98,97.72 30.4,97.72 30.25,97.87 30.25,98.09 30.4,98.24 31.98,98.24 32.13,98.39 32.13,98.6 31.23,99.49 29.77,99.49 29.61,99.34 29.61,98.58 29.46,98.42 29.24,98.42 29.09,98.58 29.09,99.34 28.94,99.49 28.72,99.49 28.57,99.34 28.57,98.58 28.42,98.42 28.2,98.42 28.05,98.58 28.05,99.34 27.9,99.49 27.68,99.49 27.53,99.34 27.53,98.58 27.38,98.42 27.16,98.42 27.01,98.58 27.01,99.34 26.85,99.49 26.51,99.49 25.71,98.7 25.71,98.08 25.86,97.92 27.28,97.92 27.43,97.77 27.43,97.56 27.28,97.4 25.86,97.4 25.71,97.25 25.71,96.89 25.96,96.65 v1(27.28,96.65)
  BOTTOM w0.13: 56.52,84.58 55.86,84.58 v1(55.6,84.84)
PRUETH0_TXD2: length 62.3
  TOP w0.13: U7.6 v1(26.81,94.59)
  L3_SIG1 w0.13: v1(58.93,85.02) 58.93,85.04 58.62,85.34 54.99,85.34 54.48,84.84 51.16,84.84 50.82,84.84 50,85.66 48.6,85.66 47.01,87.25 45.67,87.25 45.4,87.52 45.4,88.46 43.31,90.55 41.53,90.55 40.37,91.71 35.54,91.71 35.21,92.04 35.21,92.39 34.9,92.69 34.55,92.69 33.72,93.52 33.11,94.14 33.11,95.32 32.79,95.64 32.79,98.55 30.89,100.46 25.24,100.46 23.01,98.23 23.01,95.89 23.17,95.74 23.98,95.74 24.13,95.59 24.13,95.37 23.98,95.22 23.17,95.22 23.01,95.07 23.01,94.85 23.17,94.7 23.85,94.7 24,94.55 24,94.33 23.85,94.18 23.17,94.18 23.01,94.03 23.01,93.68 23.83,92.86 25.93,92.86 26.81,93.74 v1(26.81,94.59)
  BOTTOM w0.13: v1(58.93,85.02) 58.93,84.96 59.31,84.58 R377.1
PRUETH0_TXD3: length 68.8
  TOP w0.13: U7.7 v1(26.31,95.62)
  L3_SIG1 w0.13: v1(26.31,95.62) 24.78,95.62 23.88,96.52 23.88,98.3 24.26,98.68 25.02,98.68 25.27,98.42 25.27,97.03 25.28,97.02 25.28,96.71 25.78,96.21 26.55,96.21 26.72,96.03 27.44,96.03 27.95,96.54 28.33,96.54 28.48,96.69 28.48,97.1 28.63,97.26 28.85,97.26 29,97.1 29,96.69 29.15,96.54 29.93,96.54 30.12,96.35 30.33,96.35 30.97,96.98 31.18,96.98 31.34,96.83 31.34,96.62 30.7,95.98 30.7,95.76 31.35,95.12 31.35,94.27 31.84,93.78 32.23,93.78 33.07,92.95 33.07,92.25 34.85,90.47 34.85,89.15 35.2,88.8 35.2,87.53 35.46,87.27 35.81,87.27 35.99,87.45 35.99,88.01 36.4,88.42 38.24,88.42 39.73,86.93 40.88,86.93 41.7,86.12 41.87,86.12 42.02,86.27 42.02,86.94 42.17,87.1 42.39,87.1 42.54,86.94 42.54,86.27 42.69,86.12 43.22,86.12 43.37,86.27 43.37,86.54 43.52,86.69 43.74,86.69 43.89,86.54 43.89,86.27 44.04,86.12 44.26,86.12 44.41,86.27 44.41,86.54 44.56,86.69 44.78,86.69 44.93,86.54 44.93,86.27 45.09,86.12 46.72,86.12 49.11,83.73 49.11,83.66 49.52,83.25 50.27,83.25 50.42,83.4 50.42,83.74 50.57,83.9 50.79,83.9 50.94,83.74 50.94,83.4 51.09,83.25 51.31,83.25 51.46,83.4 51.46,83.74 51.61,83.9 51.83,83.9 51.98,83.74 51.98,83.4 52.14,83.25 52.35,83.25 52.5,83.4 52.5,83.74 52.66,83.9 52.87,83.9 53.02,83.74 53.02,83.4 53.18,83.25 53.39,83.25 53.55,83.4 53.55,83.74 53.7,83.9 53.91,83.9 54.07,83.74 54.07,83.4 54.22,83.25 54.64,83.25 55.56,84.16 56.02,84.16 56.29,84.43 56.29,84.71 56.44,84.86 56.65,84.86 56.81,84.71 56.81,83.45 56.96,83.3 57.18,83.3 57.33,83.45 57.33,84.71 57.48,84.86 57.7,84.86 57.85,84.71 57.85,84.2 58.23,83.82 58.74,83.82 v1(59.25,83.31)
  BOTTOM w0.13: R390.1 v1(59.25,83.31)
PRUETH0_TXEN: length 71
  TOP w0.13: U7.3 v1(28.31,95.62)
  L3_SIG1 w0.13: v1(28.31,95.62) 29.35,95.62 29.72,95.25 29.72,93.64 31.66,91.7 32.39,91.7 32.84,91.26 33.51,90.58 33.51,87.55 35.23,85.83 40.21,85.83 41.33,84.71 41.33,83.95 41.8,83.48 42.01,83.48 42.38,83.85 42.6,83.85 42.75,83.69 42.75,83.48 42.38,83.11 42.38,82.89 43.03,82.25 43.36,82.25 43.51,82.4 43.51,83.29 43.66,83.44 43.88,83.44 44.03,83.29 44.03,82.4 44.18,82.25 44.6,82.25 44.78,82.07 44.78,81.23 44.9,81.11 44.97,81.11 45.13,80.95 45.13,80.24 45.28,80.09 45.49,80.09 45.65,80.24 45.65,80.95 45.8,81.11 47.02,81.11 47.17,80.95 47.17,80.26 47.32,80.11 47.54,80.11 47.69,80.26 47.69,80.95 47.84,81.11 48.06,81.11 48.21,80.95 48.21,80.26 48.37,80.11 48.58,80.11 48.73,80.26 48.73,80.95 48.89,81.11 49.86,81.11 50.02,80.95 50.02,80.32 50.17,80.16 50.39,80.16 50.54,80.32 50.54,80.95 50.69,81.11 53.61,81.11 53.77,80.95 53.77,80.74 53.61,80.58 51.74,80.58 51.59,80.43 51.59,80.22 51.74,80.06 53.61,80.06 53.77,79.91 53.77,79.7 53.61,79.54 51.74,79.54 51.59,79.39 51.59,79.17 51.74,79.02 54.14,79.02 54.29,79.17 54.29,80.95 54.44,81.11 54.83,81.11 55.2,81.48 55.2,82.15 55.63,82.58 56.65,82.58 56.8,82.42 56.8,80.29 56.96,80.14 57.17,80.14 57.32,80.29 57.32,82.42 57.48,82.58 58.98,82.58 59.25,82.31 v1(59.25,81.91)
  BOTTOM w0.13: R405.1 v1(59.25,81.91)
PRUETH1_25MHZCLK: length 46.2
  TOP w0.13: v1(28.83,62.61) 28.83,62.74 28.81,62.76 U12.23
  L3_SIG1 w0.13: v1(16.76,99.95) 15.88,99.06 15.88,97.03 17.14,95.76 17.14,82.42 17.91,81.66 17.91,75.69 23.24,70.36 23.24,67.82 24.89,66.17 24.89,65.02 27.3,62.61 v1(28.83,62.61)
  BOTTOM w0.13: R312.2 v1(16.76,99.95)
PRUETH1_COL: length 159
  TOP w0.13: 32.89,65.66 32.2,65.66 v1(32.16,65.63) 31.53,66.26 U12.29 ; v1(75.06,85.01) R85.1
  L3_SIG1 w0.13: v1(26.16,104.14) 27.36,105.33 42.41,105.33 43.9,103.84 59.13,103.84 60,104.71 66.99,104.71 67.39,104.32 67.41,104.32 68.96,102.77 68.96,102.21 69.84,101.33 69.84,99.91 71.23,98.51 71.23,98.03 72.48,96.77 74.3,96.77 74.86,96.2 75.88,96.2 76.94,95.15 76.94,93.72 77.47,93.19 77.47,92.63 78.36,91.74 78.36,91.23 76.46,89.33 75.46,89.33 75.06,88.93 v1(75.06,85.01) ; v2(58.04,57.4) 54.16,57.4 51.82,59.74 51.82,59.74 49.99,61.57 48.32,61.57 47.09,62.81 37.59,62.81 36.49,63.91 34.77,63.91 34.77,63.91 33.88,63.91 v1(32.16,65.63)
  L4_SIG2 w0.13: v1(32.16,65.63) 32.67,66.13 32.67,73.84 29.92,76.58 28.79,76.58 27.43,77.94 27.43,83.99 25.84,85.59 25.84,95.47 24.89,96.42 24.89,102.87 v1(26.16,104.14)
  BOTTOM w0.13: v2(58.04,57.4) 61.19,54.25 63.43,54.25 64.06,54.89 64.24,54.89 64.67,55.33 64.67,55.85 64.34,56.18 64.08,56.18 R473.1 ; v1(32.16,65.63) 32.89,65.63 32.89,64.48
PRUETH1_CRS: length 3.7
  TOP w0.13: 32.89,63.34 30.98,65.26 U12.27
PRUETH1_INT: length 3.7
  TOP w0.13: TP8.1 25.81,71.47 U12.8
PRUETH1_LINKLED: length 26.8
  TOP w0.13: U12.17 25.36,63.53 24.86,63.03 24.86,62.8 24.38,62.32 v1(24.38,62.23) 24.13,61.98 R145.1
  L3_SIG1 w0.13: v1(4.29,65.99) 8.66,65.99 13.23,61.42 16.33,61.42 17.14,62.23 v1(19.18,62.23)
  L4_SIG2 w0.13: v1(24.38,62.23) v1(19.18,62.23)
  BOTTOM w0.13: R448.2 2.8,65.99 v1(4.29,65.99)
PRUETH1_MDC: length 2.3
  TOP w0.13: R147.1 27.05,61.85 27.05,62.23 27.31,62.49 U12.20
PRUETH1_MDIO: length 3.8
  TOP w0.13: U12.19 26.81,62.5 26.58,62.27 v1(26.16,62.27) 25.76,62.27 25.53,62.03 R146.1
  BOTTOM w0.13: v1(26.16,62.27) 26.2,62.23 R462.1
PRUETH1_RESETN: length 38.3
  TOP w0.13: v1(14.84,77.6) 14.84,77.02 9.14,71.32 9.14,65.63 13.69,61.09 16.76,61.09 18.41,59.44 24.26,59.44 24.89,60.07 24.89,62.1 25.53,62.74 26.16,62.74 26.31,62.89 U12.18
  BOTTOM w0.13: U44.4 v1(14.84,77.6)
PRUETH1_RXCLK: length 9.3
  TOP w0.13: U12.25 30.61,64.26 30.86,64.01 30.86,63.63 31.5,62.99 32.26,62.99 34.16,61.09 v1(34.16,59.69)
  BOTTOM w0.13: v1(34.16,59.69) 33.57,59.69 32.89,60.37 32.89,61.09
PRUETH1_RXD0: length 3.6
  TOP w0.13: U12.30 32.02,66.76 v1(32.19,66.93) 32.89,66.93
  BOTTOM w0.13: 32.89,66.93 v1(32.19,66.93)
PRUETH1_RXD1: length 4.1
  TOP w0.13: 32.89,68.07 32.07,68.07 v1(32.04,68.04) 31.25,67.26 U12.31
  BOTTOM w0.13: 32.89,68.07 32.07,68.07 v1(32.04,68.04)
PRUETH1_RXD2: length 4.4
  TOP w0.13: U12.32 30.55,67.76 v1(32,69.22) 32.89,69.22
  BOTTOM w0.13: 32.89,69.22 v1(32,69.22)
PRUETH1_RXD3: length 5.9
  TOP w0.13: 32.89,70.36 v1(32.13,70.36) 29.84,70.36 29.31,69.82 U12.1
  BOTTOM w0.13: 32.89,70.36 v1(32.13,70.36)
PRUETH1_RXDV: length 4.6
  TOP w0.13: v1(31.47,63.83) 31.47,64.15 31,64.62 30.86,64.76 U12.26
  BOTTOM w0.13: v1(31.47,63.83) 31.47,62.89 32.13,62.23 32.89,62.23
PRUETH1_RXERR: length 3.4
  TOP w0.13: 32.89,64.52 32.33,64.52 31.09,65.76 U12.28
PRUETH1_TXCLK: length 49.3
  TOP w0.13: v1(29.72,71.37) 28.81,70.46 U12.2 ; R141.1 v1(62.93,62.74)
  L3_SIG1 w0.13: v1(29.72,71.37) 38.15,71.37 42.21,67.31 44.81,67.31 45.17,66.94 47.46,66.94 47.65,67.13 47.65,67.83 47.84,68.02 48.11,68.02 48.3,67.83 48.3,67.13 48.49,66.94 48.76,66.94 48.95,67.13 48.95,67.83 49.14,68.02 49.41,68.02 49.6,67.83 49.6,67.13 49.79,66.94 50.06,66.94 50.25,67.13 50.25,67.83 50.45,68.02 50.72,68.02 50.91,67.83 50.91,67.13 51.1,66.94 51.37,66.94 51.56,67.13 51.56,67.83 51.75,68.02 52.02,68.02 52.21,67.83 52.21,67.13 52.4,66.94 52.67,66.94 52.86,67.13 52.86,67.83 53.05,68.02 53.32,68.02 53.51,67.83 53.51,67.13 53.7,66.94 53.96,66.94 58.17,62.74 v1(62.93,62.74)
PRUETH1_TXD0: length 43.7
  TOP w0.13: U12.4 v1(27.81,69.31)
  L3_SIG1 w0.13: v1(27.81,69.31) 28.65,69.31 31.72,66.24 32.49,66.24 33.68,65.05 36.98,65.05 37.31,64.72 37.31,63.7 37.77,63.24 47.27,63.24 48.46,62.05 50.65,62.05 54.29,58.4 55.17,58.4 55.32,58.25 55.32,58.01 55.48,57.86 55.69,57.86 55.84,58.01 55.84,58.25 56,58.4 59.58,58.4 60.58,57.4 v1(61.47,57.4)
  BOTTOM w0.13: v1(61.47,57.4) 61.99,57.4 63.63,59.04 R469.1
PRUETH1_TXD1: length 46.5
  TOP w0.13: U12.5 v1(27.31,70.35) ; 60.58,59.31 v1(59.69,59.31)
  L3_SIG1 w0.13: v1(27.31,70.35) 28.99,70.35 30.65,68.69 37.2,68.69 39.39,66.5 39.39,66.29 38.86,65.75 38.86,65.54 39.01,65.39 39.22,65.39 39.76,65.92 39.97,65.92 40.36,65.53 44.09,65.53 44.28,65.34 44.28,64.38 44.48,64.19 44.75,64.19 44.94,64.38 44.94,65.34 45.13,65.53 45.4,65.53 45.59,65.34 45.59,64.38 45.78,64.19 46.05,64.19 46.24,64.38 46.24,65.34 46.43,65.53 46.79,65.53 46.99,65.33 46.99,64.44 47.14,64.29 48.36,64.29 49.27,63.37 49.54,63.1 50.82,63.1 54.65,59.27 59.65,59.27 v1(59.69,59.31)
PRUETH1_TXD2: length 52
  TOP w0.13: R153.1 63.03,57.88 62.86,57.71 62.86,57.56 v1(62.86,57.56) ; U12.6 v1(26.81,69.31)
  L3_SIG1 w0.13: v1(26.81,69.31) 27.65,68.47 28.88,68.47 29.84,67.51 29.84,67.28 34.23,62.89 36.3,62.89 37.57,61.62 40.67,61.62 41.55,60.73 42.16,60.73 42.35,60.92 42.35,62.01 42.54,62.2 42.81,62.2 43,62.01 43,60.92 43.19,60.73 43.46,60.73 43.65,60.92 43.65,62.01 43.84,62.2 44.11,62.2 44.3,62.01 44.3,60.92 44.49,60.73 44.76,60.73 44.95,60.92 44.95,62.01 45.14,62.2 45.41,62.2 45.61,62.01 45.61,60.92 45.8,60.73 46.66,60.73 46.85,60.92 46.85,61.33 47.04,61.52 47.31,61.52 47.5,61.33 47.5,60.92 47.69,60.73 50.22,60.73 54.05,56.9 62.2,56.9 v1(62.86,57.56)
PRUETH1_TXD3: length 50.2
  TOP w0.13: R151.1 62.9,59.15 v1(62.86,59.18) ; U12.7 v1(26.31,70.35)
  L3_SIG1 w0.13: v1(62.86,59.18) 62.86,58.8 61.98,57.91 60.71,57.91 59.78,58.84 54.47,58.84 50.83,62.48 48.64,62.48 47.45,63.68 41.96,63.68 41.8,63.83 41.8,64.36 41.65,64.52 41.43,64.52 41.28,64.36 41.28,63.83 41.13,63.68 40.91,63.68 40.76,63.83 40.76,64.36 40.61,64.52 40.39,64.52 40.24,64.36 40.24,63.83 40.09,63.68 39.87,63.68 39.72,63.83 39.72,64.36 39.57,64.52 39.35,64.52 39.2,64.36 39.2,63.83 39.04,63.68 38.2,63.68 37.95,63.93 37.95,65.91 36.93,66.93 33.3,66.93 32.72,67.51 31.09,67.51 28.82,69.78 26.87,69.78 v1(26.31,70.35)
PRUETH1_TXEN: length 46.2
  TOP w0.13: U12.3 28.31,70.24 v1(27.3,71.25) ; v1(58.8,55.5) 59.94,55.5 R155.1
  L3_SIG1 w0.13: v1(58.8,55.5) 58.28,56.02 55.08,56.02 54.69,56.41 53.47,56.41 49.68,60.2 38.15,60.2 36.12,62.23 34.28,62.23 29.36,67.15 29.36,67.37 28.74,68 27.46,68 25.79,69.67 25.79,70.53 26.5,71.25 v1(27.3,71.25)
PRUETHER0_RDN: length 18.5
  TOP w0.102: U7.9 24.49,93.03 24.38,92.93 24.13,92.93 23.27,93.79 23.27,96.07 22.75,96.58 21.15,96.58 R31.2 19.71,96.54 18.94,96.54 17.87,95.46 17.87,94.19 16.89,93.22 15.4,93.22 14.57,94.05 14.57,94.72 14.61,94.81 14.75,94.85 J6.2
PRUETHER0_RDP: length 18.6
  TOP w0.102: J6.1 14.31,95.07 14.35,94.94 14.27,94.79 14.27,93.93 15.28,92.92 17.01,92.92 18.16,94.07 18.16,95.34 19.07,96.25 20.43,96.25 R43.2 20.47,96.29 22.63,96.29 22.97,95.95 22.97,93.67 24.01,92.63 24.38,92.63 24.49,92.53 U7.10
PRUETHER0_TDN: length 17.7
  TOP w0.102: U7.11 24.44,92.03 24.36,91.95 23.66,91.95 23.24,92.37 21.3,92.37 R50.2 20.45,93.19 19.63,92.37 18.58,92.37 18.16,91.95 18.16,88.65 17.65,88.14 15.11,88.14 14.57,88.68 14.57,89.64 14.61,89.73 14.75,89.77 J6.6
PRUETHER0_TDP: length 17.6
  TOP w0.102: J6.5 14.31,89.99 14.35,89.86 14.27,89.71 14.27,88.56 14.99,87.84 17.78,87.84 18.46,88.52 18.46,91.83 18.7,92.08 20.45,92.08 23.11,92.08 23.54,91.65 24.24,91.65 24.36,91.53 U7.12
PRUETHER1_RDN: length 29.4
  TOP w0.102: U12.9 24.49,67.76 24.38,67.65 24.13,67.65 23.49,68.3 23.49,69.17 23.04,69.62 23.04,70.75 21.78,72.01 R101.2 18.59,72.01 17.58,73.02 15.35,73.02 15.21,73.17 11.88,73.17 11.14,72.43 11.14,66.45 12.6,64.99 13.93,64.99 14.66,65.72 14.85,65.72 J9.6
PRUETHER1_RDP: length 29.2
  TOP w0.102: U12.10 24.49,67.26 24.38,67.36 24.01,67.36 23.19,68.17 23.19,69.05 22.74,69.5 22.74,70.62 21.66,71.7 21.16,71.7 R106.2 19.73,71.71 18.47,71.71 17.45,72.73 16.12,72.73 16.03,72.64 16.03,72.43 15.94,72.34 15.81,72.34 15.72,72.43 15.72,72.64 15.63,72.73 15.23,72.73 15.09,72.87 12,72.87 11.43,72.3 11.43,66.57 12.72,65.28 13.8,65.28 14.16,65.64 14.15,65.64 14.28,65.76 14.28,65.96 14.18,66.05 J9.5
PRUETHER1_TDN: length 29.1
  TOP w0.102: J9.2 14.94,70.76 14.71,70.76 14.57,70.61 14.57,69.86 15.24,69.19 17.07,69.19 17.37,68.88 17.37,68.44 17.46,68.35 18.69,68.35 18.95,68.09 18.95,67.71 18.69,67.45 17.46,67.45 17.37,67.36 17.37,63.35 17.49,63.24 18.14,63.24 18.43,63.52 18.43,63.98 18.69,64.25 20.29,64.25 20.38,64.33 20.38,64.46 20.29,64.55 18.69,64.55 18.43,64.81 18.43,66.49 19.03,67.1 19.6,67.1 R125.2 21.3,67.1 23.24,67.1 23.66,66.67 24.36,66.67 24.44,66.76 U12.11
PRUETHER1_TDP: length 29.1
  TOP w0.102: U12.12 24.51,66.26 24.39,66.38 23.54,66.38 23.11,66.8 R131.2 19.15,66.8 18.72,66.37 18.72,64.93 18.81,64.84 20.41,64.84 20.68,64.58 20.68,64.21 20.41,63.95 18.81,63.95 18.72,63.86 18.72,63.4 18.26,62.94 17.36,62.94 17.08,63.23 17.08,67.49 17.34,67.75 18.56,67.75 18.65,67.84 18.65,67.96 18.56,68.05 17.34,68.05 17.08,68.31 17.08,68.76 16.95,68.89 15.12,68.89 14.27,69.74 14.27,71.04 14.18,71.13 J9.1
RT_MII0_RXDV: length 89
  TOP w0.13: R63.1 v1(64.39,89.15) ; J3.3 8.7,103.57 15.24,103.57 15.78,103.03 19.87,103.03 22.09,100.81 27.22,100.81 27.76,100.28 33.28,100.28 34.09,101.09 34.09,101.09 34.41,101.41 45.33,101.41 46.51,102.58 56.27,102.58 v1(57.19,101.66)
  BOTTOM w0.13: v1(57.19,101.66) 57.19,101.17 55.28,99.25 55.25,99.25 53.87,97.88 53.87,93.45 53.22,92.8 53.22,88.18 55.48,85.92 57.97,85.92 58.17,86.13 59.71,86.13 59.95,85.89 61.94,85.89 63.25,84.59 65.51,84.59 66.19,85.27 66.19,87.35 v1(64.39,89.15)
RT_MII0_TXEN: length 91.2
  TOP w0.13: v1(56.98,98.88) 56.33,99.53 56.33,101.63 55.69,102.28 46.63,102.28 45.46,101.1 34.54,101.1 34.4,100.96 33.4,99.97 27.63,99.97 27.09,100.5 21.97,100.5 21.09,101.38 8.35,101.38 J3.1
  L3_SIG1 w0.13: v1(66.16,81.68) 66.16,85.84 v1(65.66,86.34)
  BOTTOM w0.13: v1(56.98,98.88) 56.92,98.88 54.93,96.88 54.93,96.15 55.09,95.99 55.09,92.48 53.55,90.94 53.55,88.29 55.59,86.25 57.86,86.25 58.09,86.48 59.79,86.48 60.05,86.22 65.54,86.22 v1(65.66,86.34) ; v1(66.16,81.68) 66.13,81.71 65.74,81.71 65.53,81.91 R404.1
RT_MII1_RXDV: length 61.5
  L3_SIG1 w0.13: J3.4 8.43,106.38 8.43,103.45 8.95,102.94 10.74,102.94 12.83,100.85 12.83,97.79 11.3,96.27 11.3,87.12 12.83,85.6 12.83,81.91 v1(12.32,81.41)
  BOTTOM w0.13: v1(12.32,81.41) 16.38,81.41 25.4,72.39 27.56,72.39 30.1,69.85 30.1,66.04 32.89,63.25
RT_MII1_TXEN: length 111.3
  TOP w0.13: R157.2 56.77,54.61 54.36,52.2 50.01,52.2 45.19,47.37 33.4,47.37 32.77,48.01 30.99,48.01 30.23,47.24 v1(30.23,47.12)
  L3_SIG1 w0.13: v1(30.23,47.12) 29.34,48.01 29.34,52.17 26.21,55.3 23.88,55.3 21.48,57.7 21.48,61.5 21.17,61.8 21.08,61.8 17.85,65.03 17.85,69.72 12.58,74.99 12.58,77.15 11.38,78.36 11.38,81.66 12.14,82.42 12.14,85.14 10.61,86.67 10.61,96.65 11.88,97.92 11.88,99.93 10.77,101.05 6.52,101.05 3.4,104.17 3.4,106.53 J3.2
RT_MII_EDIO_DATA0: length 98.4
  L3_SIG1 w0.13: J3.5 11.05,106.55 11.05,108.64 13.72,111.31 18.67,111.31 21.08,108.9 21.08,106.2 23.13,104.15 25.49,104.15 25.97,103.67 30.08,103.67 30.83,102.92 46.88,102.92 47.49,103.53 60.11,103.53 60.18,103.47 62.5,103.47 62.9,103.06 66.29,103.06 67.69,101.66 68.11,101.66 69.53,100.24 69.53,99.78 70.92,98.39 70.92,97.78 73.48,95.22 74.6,95.22 v1(76.91,92.91)
  BOTTOM w0.13: v1(76.91,92.91) 76.91,92.02 75.91,91.02 75.91,89.83 78.34,87.39 81.86,87.39 82.2,87.73 84.17,87.73 84.81,87.09 84.81,84.61 R382.1
RT_MII_EDIO_DATA1: length 93.2
  L3_SIG1 w0.13: J3.7 13.39,106.35 13.39,110.29 14.1,111 18.54,111 20.77,108.77 20.77,106.07 23,103.84 25.36,103.84 25.84,103.36 29.95,103.36 30.7,102.61 47,102.61 47.59,103.2 60.01,103.2 60.55,102.66 61.3,102.66 62.88,101.07 62.88,100.71 63.24,100.34 68.53,100.34 70.61,98.26 70.61,97.1 71.26,96.46 71.26,95.37 75.22,91.41 v1(75.6,91.41)
  BOTTOM w0.13: R384.1 83.19,84.84 82.42,85.6 82.42,86.36 81.7,87.09 76.82,87.09 75.6,88.31 v1(75.6,91.41)
RTCK: length 3
  TOP w0.13: J7.9 v1(137.67,79.5)
  BOTTOM w0.13: v1(137.67,79.5) R413.1
SD0_CLKIN: length 2.5
  TOP w0.13: J16.3 125.35,5.84 R265.1
SD_CLKIN: length 2.6
  TOP w0.13: R264.1 123.35,8.35 J16.5
SD_DATA_IN0_SD_CLKOUT: length 2.6
  TOP w0.13: J16.7 121.35,8.32 R263.1
SD_DATA_IN1: length 2.6
  TOP w0.13: R262.1 119.25,5.94 J16.9
SD_DATA_IN2: length 2.5
  TOP w0.13: R261.1 J16.11
SD_DATA_IN3: length 2.6
  TOP w0.13: J16.13 115.35,8.35 R260.1
SD_DATA_IN4: length 2.6
  TOP w0.13: R259.1 113.35,8.32 J16.15
SD_DATA_IN5_PR1_EDC_LATCH0_IN: length 2.9
  TOP w0.13: R258.1 112.27,6.76 J16.17
SD_DATA_IN6: length 2.6
  TOP w0.13: R255.1 109.22,7.24 109.35,7.11 J16.19
SD_DATA_IN7: length 2.6
  TOP w0.13: R254.1 107.35,8.35 J16.21
SENSOR_HREF: length 21.7
  TOP w0.13: v1(131.72,96.62) 131.72,97.99 132.43,98.69 134,98.69 134.57,99.26 134.57,100.51 134.11,100.97 133.06,100.97 132.22,101.8 126.67,101.8 125.78,102.69 124,102.69 122.4,104.29 J5.8
  BOTTOM w0.13: U38.10 v1(131.72,96.62)
SENSOR_PCLK: length 21.3
  TOP w0.13: J5.13 120.8,99.46 120.14,98.81 119,98.81 118.24,98.04 118.24,96.27 118.98,95.52 119.43,95.52 119.54,95.64 119.54,96.41 119.65,96.52 119.82,96.52 119.93,96.41 119.93,95.64 120.05,95.52 120.21,95.52 120.32,95.64 120.32,96.41 120.44,96.52 120.6,96.52 120.71,96.41 120.71,95.64 120.83,95.52 120.99,95.52 121.1,95.64 121.1,96.41 121.22,96.52 121.38,96.52 121.49,96.41 121.49,95.64 121.61,95.52 121.77,95.52 121.89,95.64 121.89,96.41 122,96.52 122.16,96.52 122.28,96.41 122.28,95.64 122.39,95.52 123.34,95.52 v1(124.46,96.65)
  BOTTOM w0.13: v1(124.46,96.65) 125.33,95.77 U34.4
SENSOR_PWRDN: length 5.7
  TOP w0.13: J5.11 121.2,104.43 120.46,103.69 v1(119.57,103.69)
  BOTTOM w0.13: v1(119.57,103.69) 120.65,104.77 R305.1 120.84,104.84 R304.2
SENSOR_RESET: length 17.4
  TOP w0.13: v1(120.78,98.04) 121.6,98.86 J5.15
  BOTTOM w0.13: U38.12 133.02,97.23 132.72,97.54 129.76,97.54 128.75,98.55 121.28,98.55 v1(120.78,98.04)
SENSOR_SIO_C: length 15.5
  TOP w0.13: R15.1 123.63,106.49 123.63,106.09 124,105.72 J5.4 124,104.29 124.66,103.63 126.11,103.63 126.99,102.74 130.43,102.74 132.72,105.03 v1(132.72,105.79)
  BOTTOM w0.13: v1(132.72,105.79) 133.07,105.44 U31.5
SENSOR_SIO_D: length 15.8
  TOP w0.13: J5.2 124.8,104.31 125.09,104.01 126.88,104.01 127.64,104.77 129.79,104.77 130.36,105.35 R16.1 v1(131.06,106.87)
  BOTTOM w0.13: U31.4 133.07,102.23 131.06,104.24 v1(131.06,106.87)
SENSOR_VSYNC: length 21.3
  TOP w0.13: J5.6 123.2,104.43 124.51,103.12 125.98,103.12 126.87,102.23 132.4,102.23 133.04,101.6 134.11,101.6 135.13,100.58 135.13,98.42 133.77,97.06 132.41,97.06 v1(132.37,97.03)
  BOTTOM w0.13: U38.11 v1(132.37,97.03)
SENSOR_XCLK: length 17.4
  TOP w0.13: J5.10 v1(121.6,104.01)
  L3_SIG1 w0.13: v1(121.6,104.01) 125.49,104.01 131.95,97.55 132.72,97.55 v1(133.68,96.59)
  BOTTOM w0.13: U38.13 v1(133.68,96.59)
SENSOR_Y2: length 21.4
  TOP w0.13: U6.21 114.5,91.37 v1(115.06,90.8) ; v1(125.2,99.19) J5.24
  L3_SIG1 w0.13: v1(115.06,90.8) 116.33,92.08 121.67,92.08 122.37,92.78 122.37,92.94 122.08,93.22 122.08,93.38 122.2,93.5 122.36,93.5 122.64,93.21 122.8,93.21 122.92,93.33 122.92,93.49 122.64,93.77 122.64,93.93 122.75,94.05 122.91,94.05 123.2,93.77 123.36,93.77 123.47,93.88 123.47,94.04 123.19,94.33 123.19,94.49 123.3,94.6 123.47,94.6 123.75,94.32 123.91,94.32 125.07,95.48 125.07,97.74 125.3,97.97 125.3,99.09 v1(125.2,99.19)
SENSOR_Y3: length 22.4
  TOP w0.13: v1(125.35,101.22) 124.8,100.67 J5.23 ; U6.20 v1(113.85,91.06)
  L3_SIG1 w0.13: v1(125.35,101.22) 124.46,100.33 124.46,97.41 122.64,95.59 122.48,95.59 122.26,95.81 122.1,95.81 121.98,95.69 121.98,95.53 122.2,95.31 122.2,95.15 122.09,95.04 121.93,95.04 121.71,95.26 121.54,95.26 121.43,95.14 121.43,94.98 121.65,94.76 121.65,94.6 121.53,94.48 121.37,94.48 121.15,94.7 120.99,94.7 120.88,94.59 120.88,94.43 121.1,94.21 121.1,94.05 119.89,92.84 116.43,92.84 114.65,91.06 v1(113.85,91.06)
SENSOR_Y4: length 22.3
  TOP w0.13: v1(124.84,101.66) 124.4,101.22 J5.22 ; U6.19 v1(113.2,90.04)
  L3_SIG1 w0.13: v1(124.84,101.66) 124.02,100.84 124.02,98.62 119.76,94.36 119,94.36 118.24,93.6 116.23,93.6 114.16,91.53 113.65,91.53 113.2,91.08 v1(113.2,90.04)
SENSOR_Y5: length 21.2
  TOP w0.13: U6.18 v1(112.54,91.19) ; v1(124.33,102.11) 124,101.77 J5.21
  L3_SIG1 w0.13: v1(112.54,91.19) 114.67,93.31 114.67,93.67 115.15,94.14 116.31,94.14 117.54,95.38 120.16,95.38 123.59,98.81 123.59,101.36 v1(124.33,102.11)
SENSOR_Y6: length 21.4
  TOP w0.13: v1(123.6,102.17) J5.20 ; U6.17 v1(111.89,94.36)
  L3_SIG1 w0.13: v1(111.89,94.36) 111.89,94.36 115.08,97.55 115.53,97.55 115.65,97.67 115.65,98.06 115.76,98.17 115.92,98.17 116.04,98.06 116.04,97.67 116.15,97.55 116.31,97.55 116.43,97.67 116.43,98.06 116.54,98.17 116.7,98.17 116.82,98.06 116.82,97.67 116.93,97.55 117.49,97.55 118.11,98.17 118.11,98.87 120.24,101 122.43,101 v1(123.6,102.17)
SENSOR_Y7: length 21.3
  TOP w0.13: J5.19 123.2,101.59 v1(122.62,102.17) ; U6.16 v1(111.24,94.49)
  L3_SIG1 w0.13: v1(111.24,94.49) 113.97,97.22 113.97,97.38 113.63,97.72 113.63,97.88 113.75,98 113.91,98 114.25,97.66 114.41,97.66 114.53,97.77 114.53,97.93 114.19,98.28 114.19,98.44 114.3,98.55 114.46,98.55 114.8,98.21 114.97,98.21 116.2,99.44 117.47,99.44 119.76,101.73 122.17,101.73 v1(122.62,102.17)
SENSOR_Y8: length 21.7
  TOP w0.13: U6.15 v1(110.59,93.47) ; J5.18 122.8,99.33 v1(123.06,99.06)
  L3_SIG1 w0.13: v1(110.59,93.47) 111.67,93.47 114.18,95.98 115.7,95.98 116.84,97.12 117.69,97.12 119.63,99.06 119.93,99.06 120.04,99.17 120.04,99.83 120.16,99.95 120.32,99.95 120.43,99.83 120.43,99.17 120.55,99.06 120.71,99.06 120.82,99.17 120.82,99.83 120.94,99.95 121.1,99.95 121.21,99.83 121.21,99.17 121.33,99.06 121.49,99.06 121.61,99.17 121.61,99.83 121.72,99.95 121.88,99.95 122,99.83 122,99.17 122.11,99.06 v1(123.06,99.06)
SENSOR_Y9: length 21.6
  TOP w0.13: J5.17 122.4,99.03 122.05,98.68 v1(122.05,98.04) ; U6.14 v1(109.94,91.19)
  L3_SIG1 w0.13: v1(109.94,91.19) 111.58,91.19 114.97,94.58 115.99,94.58 117.6,96.19 118.18,96.19 118.3,96.3 118.3,97.04 118.41,97.16 118.57,97.16 118.69,97.04 118.69,96.3 118.8,96.19 118.97,96.19 119.08,96.3 119.08,97.04 119.19,97.16 119.36,97.16 119.47,97.04 119.47,96.3 119.59,96.19 120.19,96.19 v1(122.05,98.04)
